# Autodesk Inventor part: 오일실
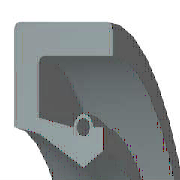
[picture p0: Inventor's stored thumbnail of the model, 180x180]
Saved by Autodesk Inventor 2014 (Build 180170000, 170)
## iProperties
IsCustomPart: 1
Created: 2015-10
Part Number: 오일실
Material: 고무
Description: 오일-실
Document SubType Name: Modeling
Standard: KS B 2804
Designer: mdu
Standards Organization: KS
Language: ko-KR
Size Designation: S - 25 38 8
Categories: <MemberInstance><Categories><Category DisplayName="샤프트 부품" InternalName="7f7aeb1f-a693-4053-b835-cee3144e0d98" Mnemonic="SHFT"><Category DisplayName="실링" Intern
Density: 0.93 g/cm^3
Appearance: 고무 - 검은색 - 버전 1.1
Mass: 2.23721 g
Surface Area: 37.0166 cm^2
Volume: 2.4056 cm^3
Author: mdu
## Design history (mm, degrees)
revolve "본체" stored, may be unused: angle "d17" = 90 deg
revolve "스프링1" stored, may be unused: angle "d18" = 90 deg
body "Solid1"
sketch "스케치1"
  geometry: L1 (0, 19)-(8, 19); L2 (8, 19)-(8, 17.75); L3 (8, 17.75)-(1.75, 17.75); L4 (0, 19)-(0, 14.6); L5 (0, 14.6)-(1.75, 14.25); L6 (1.75, 14.25)-(4.9, 12.5); L7 (4.9, 12.5)-(0, 12.5); L8 (6.3, 13.375)-(6.3, 14.6); L9 (0, 0)-(9.586, 0) reference; L10 (4.9, 12.5)-(6.3, 13.375); L11 (0, 18)-(0, -3) reference; L12 (-1.917, 0)-(11.503, 0) reference; L13 (4.2, 14.6)-(1.75, 15.09); L14 (1.75, 15.09)-(1.75, 17.75); L15 (6.3, 14.6)-(5.6, 14.6); C1 r 0.455 at (4.9, 14.6); A1 r 0.7 centre (4.9, 14.6) between (5.6, 14.6) and (4.2, 14.6)
  constraints: 26 end point, 5 horizontal alignment, 4 perpendicular, 2 centre point, 2 collinear, 2 horizontal, 2 parallel, 2 point on circle, 2 point on line, 2 vertical alignment, 1 coincident
  dimensions: "d0" = 38 diameter of L1 L9 (= SD2); "d1" = 26.75 diameter of L8.start L9 (= ABDM); "d2" = 1.25 distance of L1.end L2.end (computed from SD); "d3" = 0.91 diameter of C1 (= SPDI); "d4" = 1.4 diameter of A1 (= SPDA); "d5" = 25 diameter of L6.end L9 (= NND); "d6" = 28.5 diameter of L5.end L9 (= TKDM); "d7" = 29.2 diameter of L4.end L9 (= HLDM); "d8" = 4.9 distance from line of C1.centre L4 (= SPDST); "d9" = 6.3 distance between parallel lines of L8 L4 (= SDI); "d10" = 8 distance between parallel lines of L2 L4 (= SWDT); "d12" = 1.75 distance between parallel lines of L14 L4 (= SD)
fillet "모깎기1" dims "d11" = 0.3 (= RR)
other parameters: "SD2" = 38 [user parameter; used in 1 equation term], "SWDT" = 8 [user parameter; used in 1 equation term], "RR" = 0.3 [user parameter; used in 1 equation term], "SD" = 1.75 [user parameter; used in 2 equation terms], "NND" = 25 [user parameter; used in 1 equation term], "SPDA" = 1.4 [user parameter; used in 1 equation term], "SPDI" = 0.91 [user parameter; used in 1 equation term], "TKDM" = 28.5 [user parameter; used in 1 equation term], "HLDM" = 29.2 [user parameter; used in 1 equation term], "ABDM" = 26.75 [user parameter; used in 1 equation term], "SDI" = 6.3 [user parameter; used in 1 equation term], "SPDST" = 4.9 [user parameter; used in 1 equation term], "d13" = 0, "d14" = 0, "d15" = 0, "LAB" = 0.35 [user parameter]
